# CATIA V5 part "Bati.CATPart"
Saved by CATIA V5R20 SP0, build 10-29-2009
Part number: Bati
Bounding box of the stored display mesh (mm): x -20 to 152.5, y 0 to 305, z 0 to 523.436
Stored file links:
  C:\Users\thinkmotion1\Desktop\Khaled_IAO_Pack2\IAO_2010_1412_jclement\Non_Optimise\Bati.CATPart
  C:\Users\thinkmotion1\Desktop\Khaled_IAO_Pack2\IAO_2010_1412_jclement\Non_Optimise\Synthese IAO_2.CATProduct
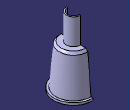
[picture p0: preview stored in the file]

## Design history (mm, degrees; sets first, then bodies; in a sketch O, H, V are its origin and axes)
Set1
  Plane1: linked copy from another document
  DatumCurve1 to DatumCurve4: linked copy from another document
  DatumSurface1: linked copy from another document
  DatumCurve5: linked copy from another document
Body1 (main body)
  Sketch1 on yz-plane, origin (0, 0, 0), H (0, 1, 0), V (0, 0, 1)
    point P1 (152.5, 0)
    line L1 (152.5, 0) -> (0, 0)
    line L2 (0, 0) -> (0, 17)
    line L3 (0, 17) -> (17, 17)
    line L4 (17, 17) -> (41.5, 306)
    line L5 (41.5, 306) -> (56.5, 323.4356)
    line L6 (56.5, 323.4356) -> (97, 323.4356)
    line L7 (97, 323.4356) -> (97, 523.4356)
    line L8 (97, 523.4356) -> (107, 523.4356)
    line L9 (152.5, 17) -> (152.5, 0)
    point P8 (152.5, 17)
    line L10 (152.5, 17) -> (27.0359, 17)
    line L11 (27.0359, 17) -> (51.1909, 301.9311)
    line L12 (51.1909, 301.9311) -> (61.0883, 313.4356)
    line L13 (61.0883, 313.4356) -> (107, 313.4356)
    line L14 (107, 313.4356) -> (107, 523.4356)
    axis line L15 (152.5, -27.6521) -> (152.5, 605.4633)
    point P14 (152.5, -27.6521)
    length L2 = 17
    length L3 = 17
    length L5 = 23
    length L4 H = 24.5
    length L4 V = 289
    length L5 H = 15
    length L7 = 200
    distance L11 L4 = 10
    distance L12 L5 = 10
    distance L13 L6 = 10
    distance L14 L7 = 10
    coincidence: P1 H, P8 L3, P14 L9
    horizontal: L1 H, L3 H, L6 H, L8 H, L10 H, L13 H
    vertical: L2 V, L7 V, L9 V, L15 V
  Shaft1: profile Sketch1, axis Sketch1.L15, angle 180
  Sketch2 on yz-plane, origin (0, 0, 0), H (0, 1, 0), V (0, 0, 1)
    circle A1 centre (226.621, 120.5037) radius 5
    reference projected circle E1 centre (226.621, 120.5037) radius 5 from edge of DatumCurve1
    coincidence: A1 E1
  Pad1: profile Sketch2, direction (-1, 0, 0), length 10, mirrored extent
  Sketch3 on yz-plane, origin (0, 0, 0), H (0, 1, 0), V (0, 0, 1)
    point P1 (229.3337, 124.7038)
    line L1 (229.3337, 124.7038) -> (269.5457, 124.7038)
    line L2 (269.5457, 124.7038) -> (269.5457, 116.3035)
    line L3 (269.5457, 116.3035) -> (229.3337, 116.3035)
    line L4 (229.3337, 116.3035) -> (229.3337, 124.7038)
    point P3 (269.5457, 116.3035)
    point P4 (229.3337, 116.3035)
    reference projected circle E1 centre (226.621, 120.5037) radius 5 from edge [end face of Pad1 | face of Pad1 from Sketch2.A1]
    reference projected circle E2 centre (226.621, 120.5037) radius 5 from edge [end face of Pad1 | face of Pad1 from Sketch2.A1]
    reference projected line E3 (277.9641, 17) -> (253.8091, 301.9311) from edge [face of Shaft1 from Sketch1.L11 | face of Shaft1]
    horizontal: L1 H, L3 H
    vertical: L2 V, L4 V
    coincidence: P1 E1, P4 E2, P3 E3
  Pad2: profile Sketch3, direction (1, 0, 0), length 5, mirrored extent
  Sketch4 on yz-plane, origin (0, 0, 0), H (0, 1, 0), V (0, 0, 1)
    circle A1 centre (152.4579, 78.384) radius 12.2498
    reference projected circle E1 centre (152.4579, 78.384) radius 12.2498 from edge of DatumCurve2
    coincidence: A1 E1
  Pad3: profile Sketch4, direction (-1, 0, 0), length 10, opposite side length 122
  Sketch5 on face of DatumSurface1, origin (0, 231.8157, 0.0098), H (1, 0, 0), V (0, -0.0108, 0.9999)
    circle A1 centre (0, 167.1841) radius 14
    circle A2 centre (0, 167.1841) radius 20
    reference projected circle E1 centre (0, 167.1841) radius 14 from edge of DatumCurve5
    radius A2 = 20
    coincidence: A1 E1
  Pad4: profile Sketch5, direction (0, -0.9999, -0.0108), length 10
  Sketch6 on yz-plane, origin (0, 0, 0), H (0, 1, 0), V (0, 0, 1)
    circle A1 centre (225.011, 167.1302) radius 5
    point P1 (225.011, 167.1302)
    reference projected line E1 (220.1679, 152.5724) -> (219.8656, 180.5708) from edge [end face of Pad4 | face of Pad4 from Sketch5.A1]
    reference projected line E2 through (0.0101, 164.7009) direction (-0.9999, -0.0108) from axis of face of Pad4 from Sketch5.A2
    radius A1 = 5
    tangency: A1 E1
    coincidence: P1 E2
  Pad5: profile Sketch6, direction (1, 0, 0), length 91
  Sketch7 on end face of Pad4, origin (0, 221.8151, 0.0098), H (1, 0, 0), V (0, -0.0108, 0.9999)
    arc A1 centre (0, 167.0762) radius 14 from (0, 153.0762) to (0, 181.0762) ccw
    reference projected circle E1 centre (0, 167.0762) radius 14 from edge [end face of Pad4 | face of Pad4 from Sketch5.A1]
    line L1 (0, 181.0762) -> (0, 153.0762)
    point P2 (0, 181.0762)
    coincidence: A1 E1, P2 V
    vertical: L1 V
  Pocket1: profile Sketch7, direction (0, 0.9999, 0.0108), length 10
